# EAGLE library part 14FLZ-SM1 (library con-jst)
CONNECTOR
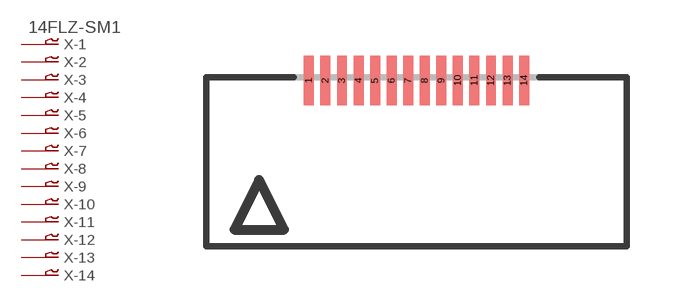
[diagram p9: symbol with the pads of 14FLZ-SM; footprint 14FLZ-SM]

Designator prefix X; gates -1=P-VN -2=P-N -3=P-N -4=P-N -5=P-N -6=P-N -7=P-N -8=P-N -9=P-N -10=P-N -11=P-N -12=P-N -13=P-N -14=P-N

## 14FLZ-SM1 (OC_FARNELL: unknown; OC_NEWARK: unknown)  [14FLZ-SM]
1  -1:1  pas
2  -2:1  pas
3  -3:1  pas
4  -4:1  pas
5  -5:1  pas
6  -6:1  pas
7  -7:1  pas
8  -8:1  pas
9  -9:1  pas
10  -10:1  pas
11  -11:1  pas
12  -12:1  pas
13  -13:1  pas
14  -14:1  pas

## Footprint 14FLZ-SM (pad centres in mm)
CONNECTOR
smd 0.3 x 1.5: 1 -3.25,2.5; 2 -2.75,2.5; 3 -2.25,2.5; 4 -1.75,2.5; 5 -1.25,2.5; 6 -0.75,2.5; 7 -0.25,2.5; 8 0.25,2.5; 9 0.75,2.5; 10 1.25,2.5; 11 1.75,2.5; 12 2.25,2.5; 13 2.75,2.5; 14 3.25,2.5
